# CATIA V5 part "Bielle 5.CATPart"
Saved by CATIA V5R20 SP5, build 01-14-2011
Part number: Bielle 5
Bounding box of the stored display mesh (mm): x -280 to -240, y -210 to 110, z -25 to -15
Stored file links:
  U:\CFAO\Thinkmotion\Bielle 5.CATPart
  U:\CFAO\Thinkmotion\Bras Articule.CATProduct
  J:\Projet Thinkmotion\areckea\Part1.CATPart
  U:\CFAO\Thinkmotion\Squelette Bielle 5.CATPart
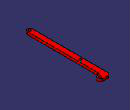
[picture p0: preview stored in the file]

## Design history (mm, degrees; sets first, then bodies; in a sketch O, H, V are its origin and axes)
Set1
  Plane1: linked copy from another document
  Line1: linked copy from another document
  Line2: linked copy from another document
  Point1 to Point3: linked copy from another document
Body1 (main body)
  Sketch1 on Plane1, origin (0, 0, -20), H (1, 0, 0), V (0, 1, 0)
    line L1 (-250, 110) -> (-280, 110)
    line L2 (-280, 110) -> (-280, -200)
    arc A1 centre (-270, -200) radius 10 from (-280, -200) to (-260, -200) ccw
    line L3 (-260, -200) -> (-260, 90)
    line L4 (-260, 90) -> (-250, 90)
    arc A2 centre (-250, 100) radius 10 from (-250, 90) to (-250, 110) ccw
    reference projected line E1 (-270, 100) -> (-270, 0) from Line1
    reference projected line E2 (-270, 100) -> (-270, 0) from Line1
    reference projected line E3 (-250, 100) -> (-270, 100) from Line2
    reference projected point E4 (-270, -200) from Point1
    reference projected point E5 (-250, 100) from Point2
    circle A3 centre (-250, 100) radius 5
    circle A4 centre (-270, 0) radius 5
    point P9 (-270, 0)
    reference projected point E6 (-270, 0) from Point3
    circle A5 centre (-270, -200) radius 5
    radius A2 = 10
    radius A1 = 10
    radius A3 = 5
    radius A4 = 5
    radius A5 = 5
    horizontal: L1 H, L4 H
    vertical: L2 V
    tangency: A1 L2, L3 A1, A2 L1, A2 L4
    symmetry: L3 L2 E1, L4 L1 E3
    parallelism: L3 L2, L2 E2
    concentricity: E4 A1, E5 A2, A3 A2, A4 E6, A5 A1
    coincidence: P9 H
  Pad1: profile Sketch1, direction (0, 0, 1), length 5, mirrored extent
  Fillet1: radius 10, on edge [face of Pad1 from Sketch1.L2 | face of Pad1 from Sketch1.L1]; edge [face of Pad1 from Sketch1.L4 | face of Pad1 from Sketch1.L3]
